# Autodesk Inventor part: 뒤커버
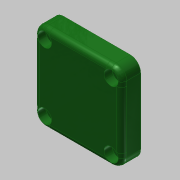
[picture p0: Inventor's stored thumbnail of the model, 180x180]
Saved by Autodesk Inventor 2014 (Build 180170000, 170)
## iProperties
Created: 2018-07
Part Number: 뒤커버
Material: 알루미늄 6061
Document SubType Name: Modeling
Designer: mduedu
Density: 1 g/cm^3
Appearance: Smooth - Dark Forest Green
Author: mduedu
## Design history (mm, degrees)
sketch "스케치1"
  geometry: C1 r 16 at (0, 0); 1 further point
  constraints: 1 centre point, 1 coincident
  dimensions: "d0" = 32 diameter of C1
extrude "돌출1" new body sketch "스케치1" distance "d1" = 3; taper "d2" = 0 deg
sketch "스케치2"
  geometry: L1 (-25, -25)-(25, -25); L2 (25, -25)-(25, 25); L3 (25, 25)-(-25, 25); L4 (-25, 25)-(-25, -25); L5 (-25, -25)-(25, 25); L6 (25, -25)-(-25, 25); 1 further point
  constraints: 12 end point, 2 midpoint, 2 parallel, 1 horizontal, 1 perpendicular
  dimensions: "d3" = 50 distance of L3.end L2.end; "d4" = 50 distance of L2.end L1.end
extrude "돌출2" join sketch "스케치2" distance "d5" = 11; taper "d6" = 0 deg
hole "구멍1" diameter "d9" = 25; stored, may be unused: countersink angle "d13" = 90 deg, drill point angle "d15" = 0 deg; dims "d7" = 10, "d8" = 10, "d10" = 6, "d11" = 4, "d12" = 2, "d14" = 3
fillet "모깎기2" dims "d26" = 3
fillet "모깎기3" dims "d27" = 6
sketch "스케치5"
  geometry: L1 (25, -19)-(25, 19) reference; L2 (19, 25)-(-19, 25) reference; L3 (-25, 19)-(-25, -19) reference; L4 (-19, -25)-(19, -25) reference; A1 r 6 centre (19, -19) between (19, -25) and (25, -19) reference; A2 r 6 centre (19, 19) between (25, 19) and (19, 25) reference; A3 r 6 centre (-19, 19) between (-19, 25) and (-25, 19) reference; A4 r 6 centre (-19, -19) between (-25, -19) and (-19, -25) reference; 5 further points
  constraints: 4 coincident
hole "구멍2" sketch "스케치5" at (-19, 19), (19, 19), (19, -19), (-19, -19) diameter "d28" = 4.5; stored, may be unused: countersink angle "d32" = 90 deg, drill point angle "d34" = 0 deg; dims "d29" = 6, "d30" = 8, "d31" = 4.6, "d33" = 3
fillet "모깎기4" dims "d35" = 3
chamfer "모따기2" distance "d36" = 1; stored, may be unused: second distance "d37" = 2, angle "d38" = 45 deg
node "솔리드1"
node "투영된 루프1"
